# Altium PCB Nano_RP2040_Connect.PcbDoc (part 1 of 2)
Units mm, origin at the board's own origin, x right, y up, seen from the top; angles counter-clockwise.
Board outline 43.18 x 17.78 mm, 4 copper layers (TOP, GND, SIG, BOTTOM), stack 1.586 mm thick; 92 components, 78 nets, 388 pads, 198 vias.
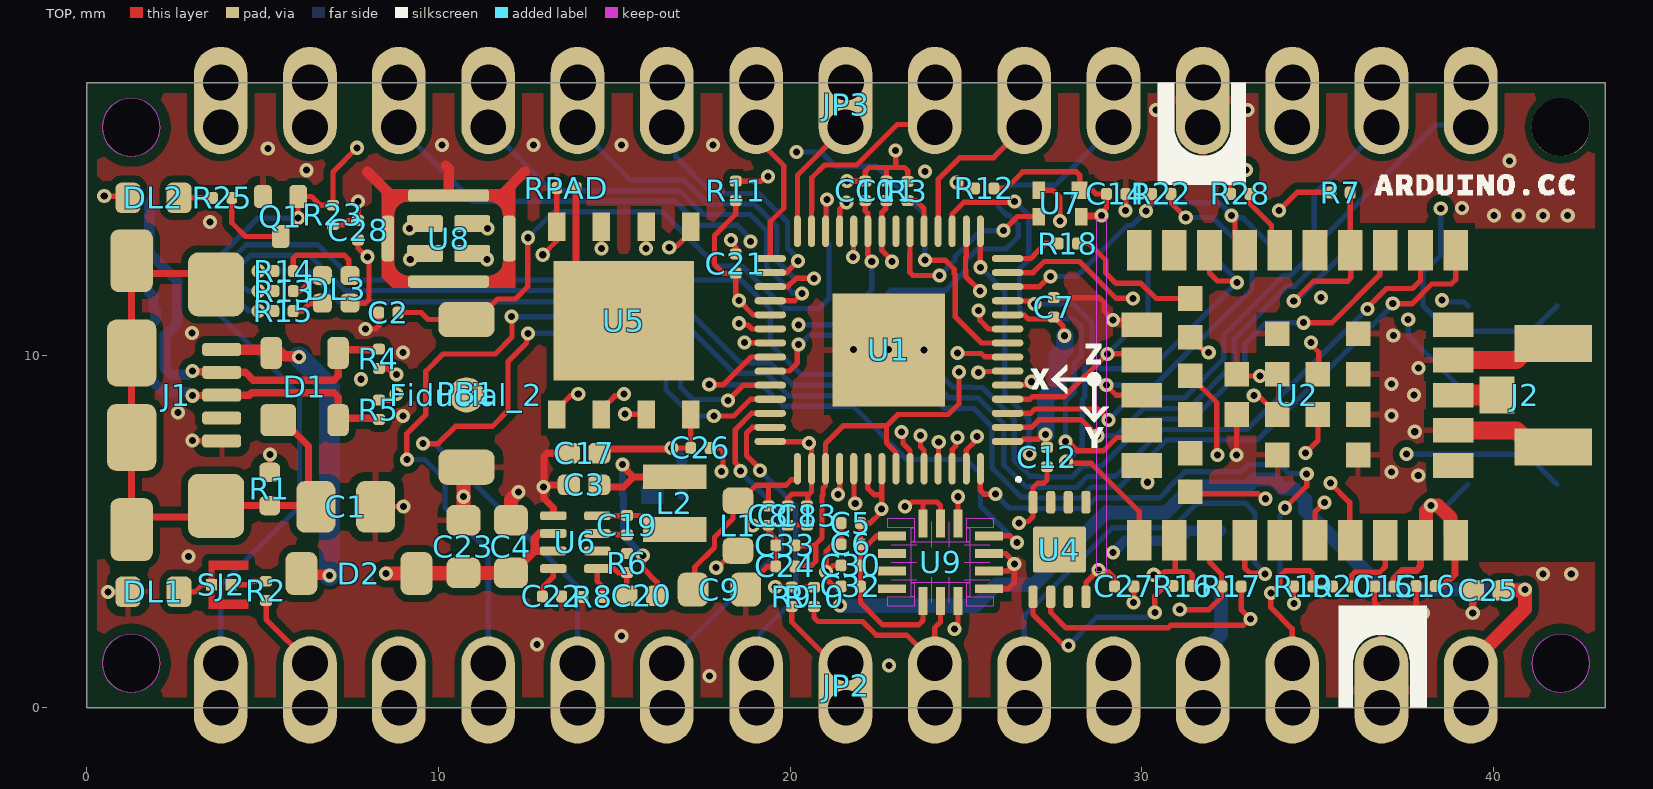
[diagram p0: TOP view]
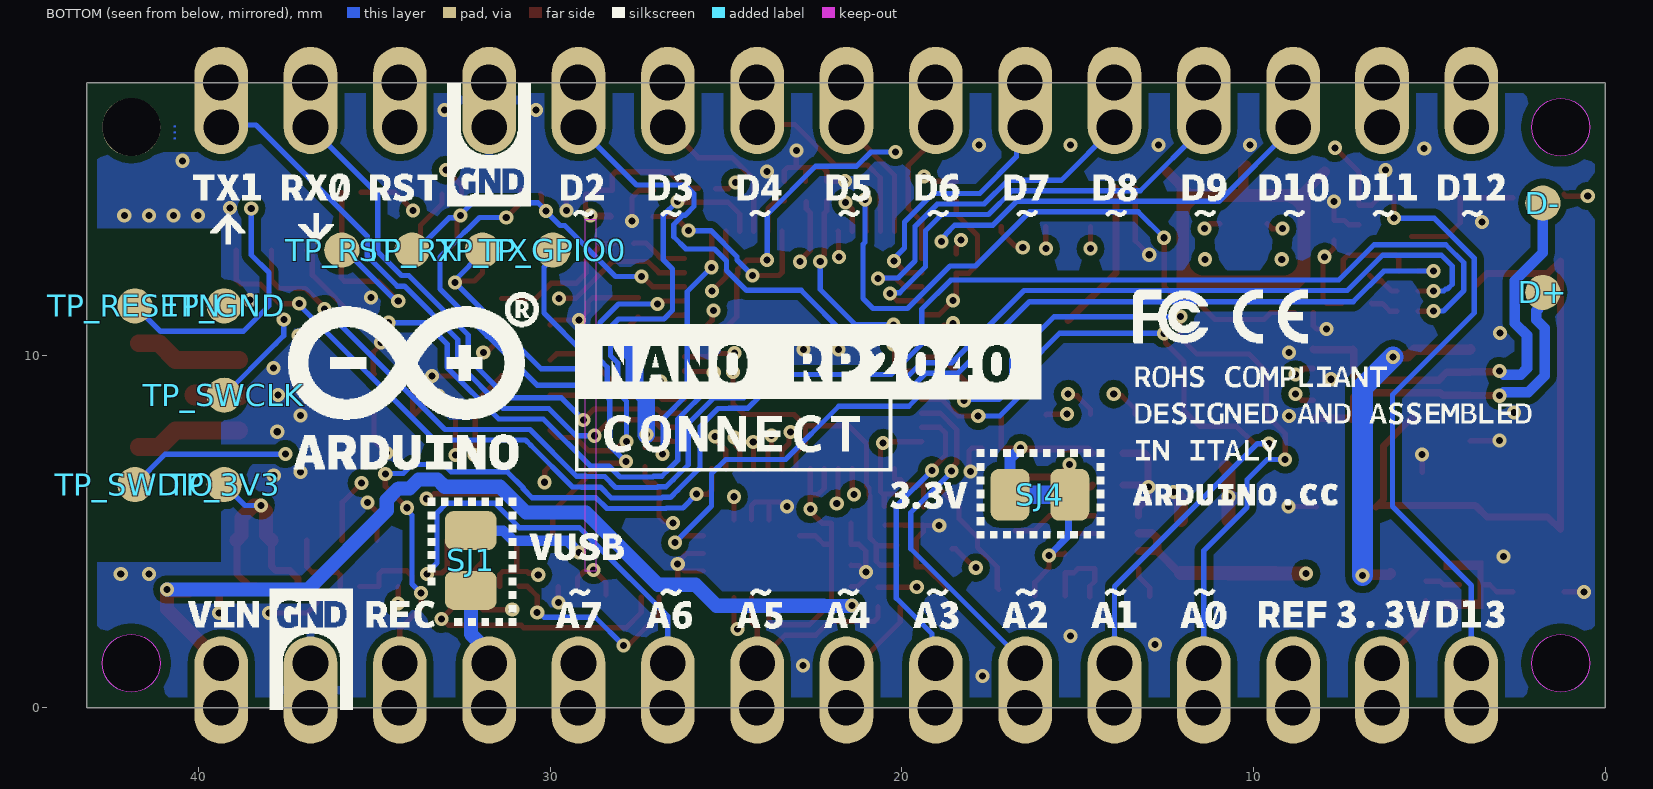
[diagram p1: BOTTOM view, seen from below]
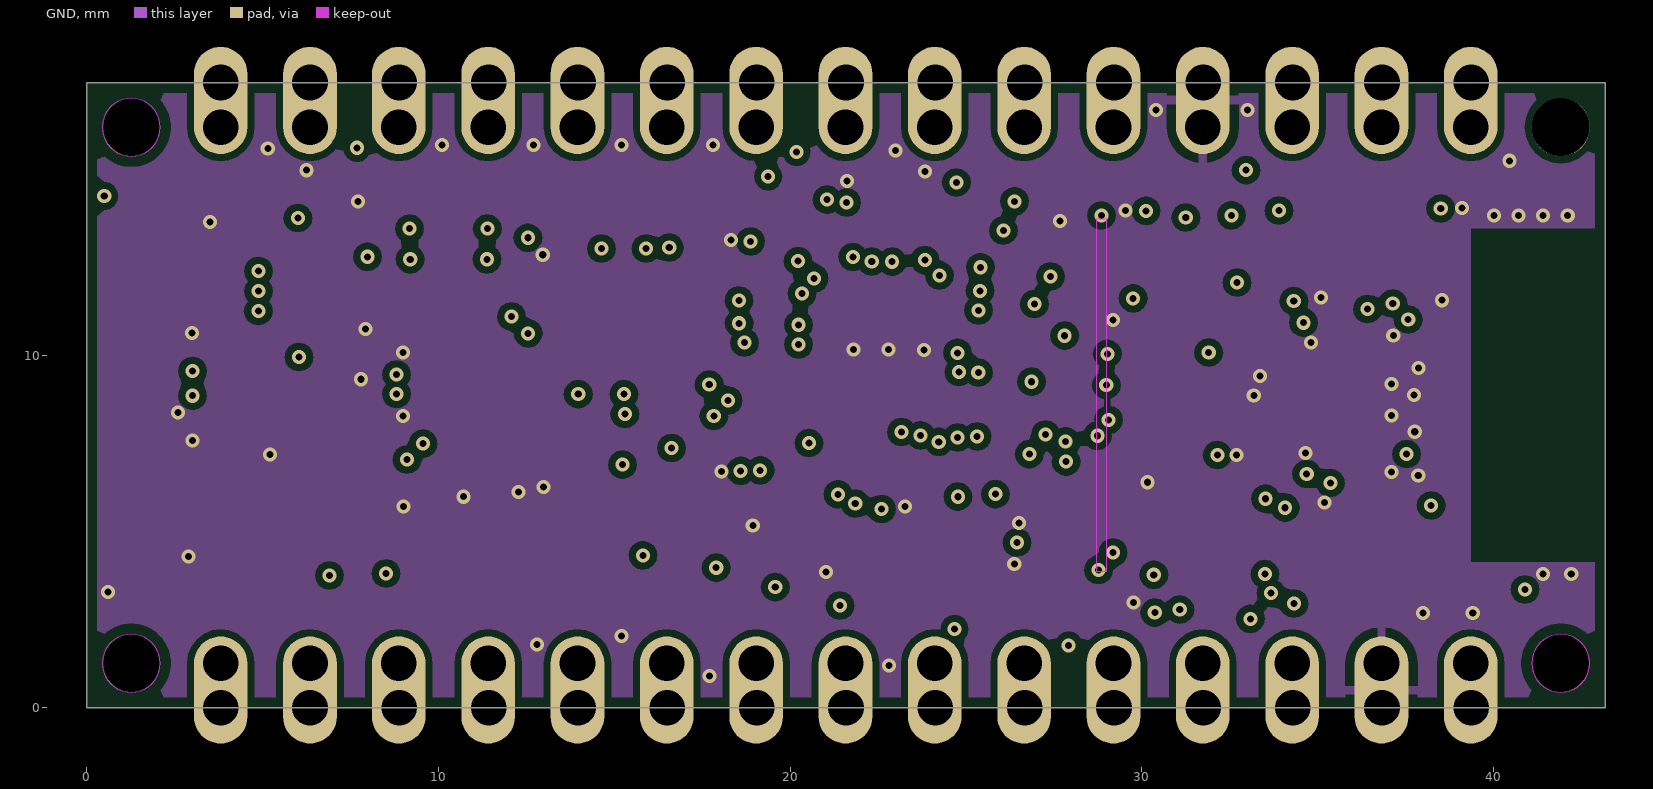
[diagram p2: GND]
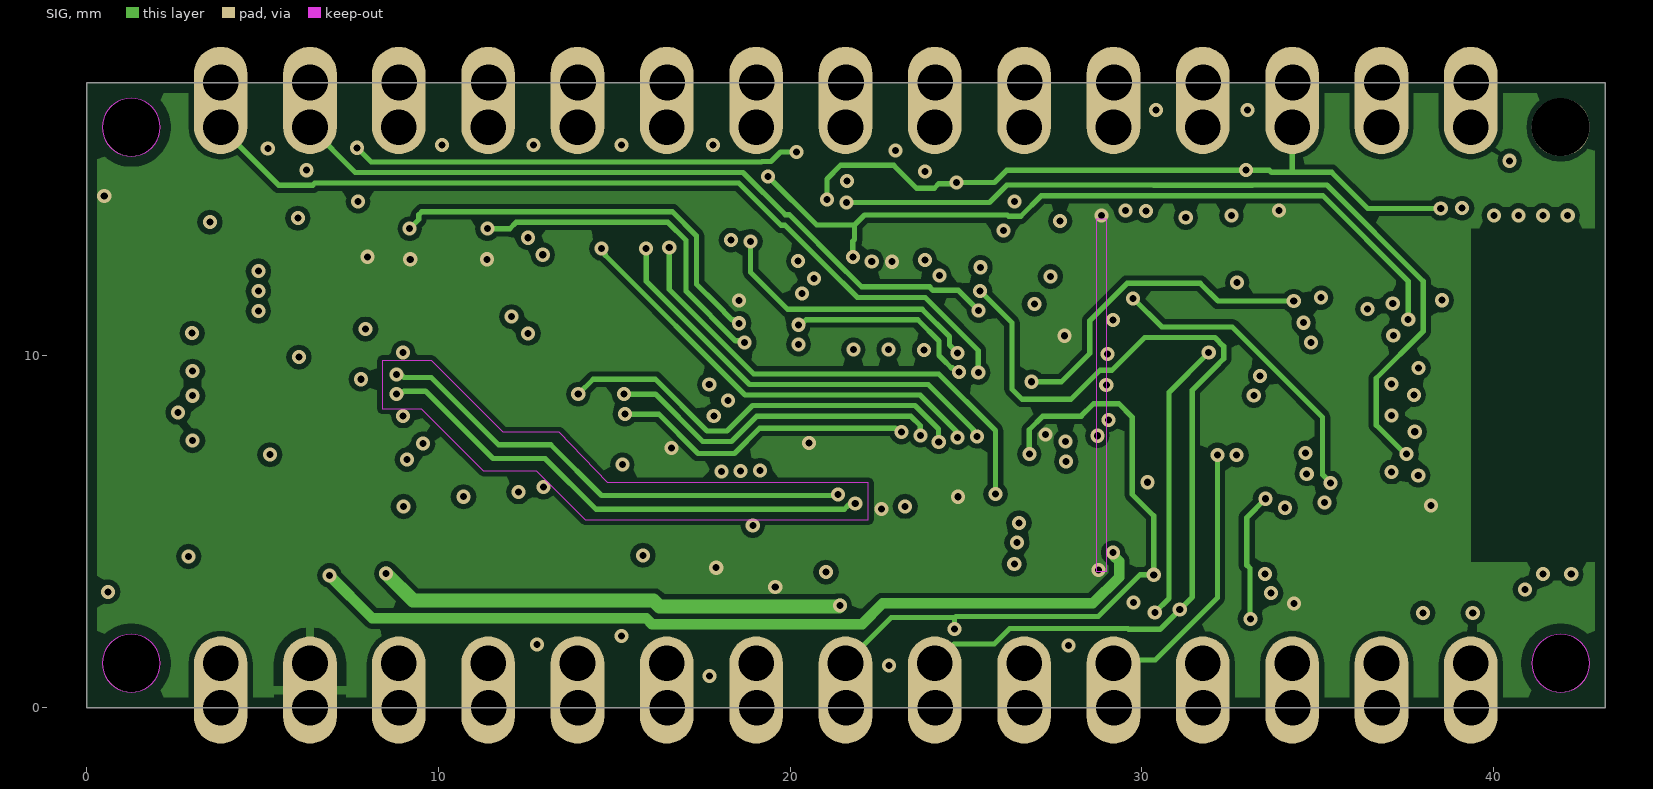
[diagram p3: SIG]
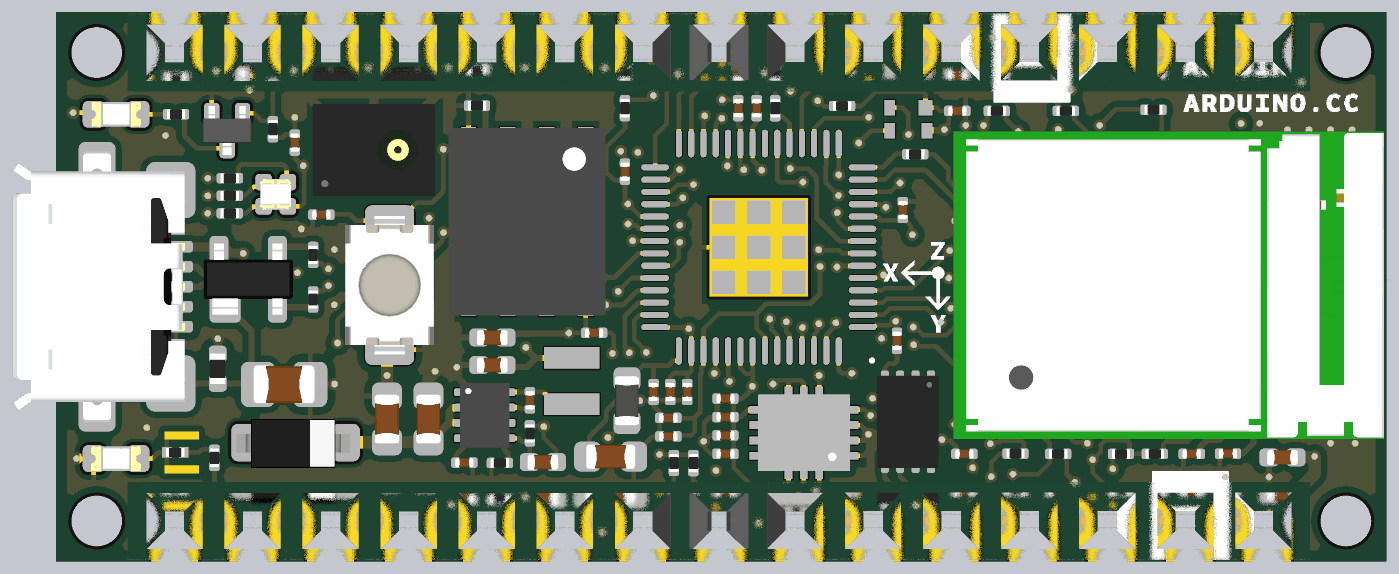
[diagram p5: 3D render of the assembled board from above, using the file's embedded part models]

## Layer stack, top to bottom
Top Solder: solder mask 0.0102, Solder Resist, Dk 3.5
TOP: signal copper 0.018
Dielectric 1: prepreg 0.14, PP-014, Dk 4.2
GND: signal copper 0.035
Dielectric2: core 1.2, FR-4, Dk 4.8
SIG: signal copper 0.035
Dielectric3: prepreg 0.14, PP-014, Dk 4.2
BOTTOM: signal copper 0.018
Bottom Solder: solder mask 0.0102, Solder Resist, Dk 3.5

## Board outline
43.174,-0.009 -0.006,-0.009 -0.006,17.771 43.174,17.771
cut-out: 41.904,0.436 ccw(c41.904,1.261) 42.73,1.261 ccw(c41.904,1.261) 41.904,2.087 ccw(c41.904,1.261) 41.079,1.261 ccw(c41.904,1.261)
cut-out: 1.264,15.676 ccw(c1.264,16.501) 2.09,16.501 ccw(c1.264,16.501) 1.264,17.327 ccw(c1.264,16.501) 0.439,16.501 ccw(c1.264,16.501)
cut-out: 1.264,0.436 ccw(c1.264,1.261) 2.09,1.261 ccw(c1.264,1.261) 1.264,2.087 ccw(c1.264,1.261) 0.439,1.261 ccw(c1.264,1.261)

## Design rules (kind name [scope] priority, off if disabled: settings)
BoardOutlineClearance Silks [(OnLayer('Top Overlay') OR OnLayer('Bottom Overlay'))] p1: gap=0.01 ignorepadtopadclearanceinfootprint=FALSE
BoardOutlineClearance MountingHoles [(ObjectKind = 'Pad') And (Name = 'Free-MH')] p2: gap=0 ignorepadtopadclearanceinfootprint=FALSE
BoardOutlineClearance Header_Castellated [((ObjectKind = 'Pad') And (Component = 'JP2')) OR                                                                                    ((ObjectKind = 'Pad') And (Component = 'JP3'))] p3: gap=0 ignorepadtopadclearanceinfootprint=FALSE
BoardOutlineClearance [All] p4: gap=0.3 ignorepadtopadclearanceinfootprint=FALSE
Clearance GND_POLYGONS [(InNamedPolygon('GND_TOP') OR InNamedPolygon('GND_2') OR InNamedPolygon('GND_3') OR InNamedPolygon('GND_BOT'))] p1: gap=0.2 ignorepadtopadclearanceinfootprint=FALSE
Clearance "Generic clearance 0.15mm" [All] p2: gap=0.15 ignorepadtopadclearanceinfootprint=FALSE
ComponentClearance NINA-UFL [InComponent('U2') vs InComponent('J2')] p1: gap=0 collisioncheckmode=3 verticalgap=0 showdistances=FALSE
ComponentClearance [All] p2: gap=0 collisioncheckmode=3 verticalgap=0 showdistances=FALSE
DiffPairsRouting [InDifferentialPairClass('USB')] p1: maxlimit=0.254 minlimit=0.15 mostfreqgap=0.254 toplayer_maxgap=0.15 toplayer_prefgap=0.15 toplayer_minwidth=0.15 toplayer_maxwidth=0.21 toplayer_prefwidth=0.21 midlayer14_mingap=0.24 midlayer14_maxgap=0.24 midlayer14_prefgap=0.24 midlayer14_minwidth=0.15 midlayer14_maxwidth=0.15 midlayer14_prefwidth=0.15 bottomlayer_maxgap=0.15 bottomlayer_prefgap=0.15 bottomlayer_minwidth=0.21 bottomlayer_maxwidth=0.21 bottomlayer_prefwidth=0.21 impedanceprofiledriven=TRUE impedanceprofileid={C5D8398E-BCA5-4495-8332-5063613C51E1} impedanceprofilevalue=90.000000 maxuncoupledlength=12.7
HoleSize [All] p1: absolutevalues=TRUE maxlimit=6 minlimit=0.2 maxpercent=80.000 minpercent=20.000
HoleToHoleClearance [All] p1: gap=0.25 allowstackedmicrovias=TRUE
MinimumAnnularRing [All] p1: minimumring=0.1
MinimumSolderMaskSliver [All] p1: minsoldermaskwidth=0.1
NetAntennae Inductor [(ObjectKind = 'Component') And (Comment = 'MAKK2016T3R3M')] p1: netantennaetolerance=10
NetAntennae [All] p2: netantennaetolerance=0
PolygonConnect [All] p1: thpad.connectstyle=Relief thpad.reliefconductorwidth=0.254 thpad.reliefentries=4 thpad.polygonreliefangle="90 Angle" thpad.airgapwidth=0.254 smdpad.connectstyle=Relief smdpad.reliefconductorwidth=0.15 smdpad.reliefentries=4 smdpad.polygonreliefangle="90 Angle" smdpad.airgapwidth=0.254 via.connectstyle=Direct via.reliefconductorwidth=0.254 via.reliefentries=4 via.polygonreliefangle="90 Angle" via.airgapwidth=0.254
RoomDefinition TOP [InComponentClass('TOP')] p1: confinementstyle=ConfineIn formatcopy=TRUE lockcomponents=FALSE outline -0.006,-0.009 43.174,-0.009 43.174,17.771 -0.006,17.771
RoutingVias [All] p1: holewidth=0.2 width=0.4 viastyle="Through Hole" minholewidth=0.2 minwidth=0.4 maxholewidth=0.2 maxwidth=0.4
ShortCircuit SJ4 [Component = 'SJ4' vs (InNet('+3V3') OR InNet('NetC3_2'))] p1: allowed=TRUE
ShortCircuit [All] p2: allowed=FALSE
SilkToSilkClearance [All] p1: silktosilkclearance=0.2
SilkToSolderMaskClearance [IsPad] p1: minsilkscreentomaskgap=0.1 clearancetoexposedcopper=TRUE
SolderMaskExpansion Solder_VIA [IsVia] p1: expansion=0.102 istentingtop=TRUE
SolderMaskExpansion [All] p2: expansion=0.102 istentingtop=FALSE
UnRoutedNet [All] p1: checkbadconnections=TRUE
ViasUnderSMD [All] p1: allowed=FALSE
Width [All] p1: maxlimit=5 minlimit=0.15 preferedwidth=0.15
20 further rules are at their usual default settings.

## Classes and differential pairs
net class 50ohm: ANT
differential pair class USB: D USB
pad class SMDPaste_OFF: D+-X D--X FD1-P$1 J3-4
differential pair USB: +USB_P -USB_N
differential pair D: +D_P -D_N

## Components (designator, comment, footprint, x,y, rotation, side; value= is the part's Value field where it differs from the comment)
C1 "C0805C472KDRACTU" CAP-0805 7.36,5.706 r180 top value=4.7nF
C2 "CL03A104KP3NNNC" CAP-0201 8.573,11.226 r180 top value=100nF
C3 "GRM155R60J106ME05D" CAP-0402 14.136,6.331 r0 top value=10µF
C4 "GRM188R61E106MA73J" CAP-0603 12.058,4.578 r270 top value=10µF
C5 "CL03A104KP3NNNC" CAP-0201 21.72,5.243 r180 top value=100nF
C6 "CL03A104KP3NNNC" CAP-0201 21.72,4.643 r180 top value=100nF
C7 "CL03A104KP3NNNC" CAP-0201 27.491,11.379 r90 top value=100nF
C8 "CL03A104KP3NNNC" CAP-0201 19.38,5.457 r270 top value=100nF
C9 "CC0603MRX5R5BB106" CAP-0603 17.985,3.355 r180 top value=10µF
C10 "CL03A104KP3NNNC" CAP-0201 22.134,14.691 r90 top value=100nF
C11 "CL03A104KP3NNNC" CAP-0201 22.734,14.691 r90 top value=100nF
C12 "CL03A104KP3NNNC" CAP-0201 27.299,7.122 r270 top value=100nF
C13 "GRM033R60J105MEA2D" CAP-0201 20.476,5.457 r270 top value=1µF
C14 "CL03A104KP3NNNC" CAP-0201 29.264,14.602 r0 top value=100nF
C15 "CL03A104KP3NNNC" CAP-0201 36.888,3.442 r180 top value=100nF
C16 "CL03A104KP3NNNC" CAP-0201 38.069,3.453 r180 top value=100nF
C17 "GRM155R60J106ME05D" CAP-0402 14.136,7.231 r0 top value=10µF
C18 "CL03A104KP3NNNC" CAP-0201 19.928,5.457 r270 top value=100nF
C19 "CL03A104KP3NNNC" CAP-0201 15.358,5.186 r270 top value=100nF
C20 "C0402C220J5GAC7411" CAP-0402 15.78,3.176 r0 top value=22pF
C21 "CL03A104KP3NNNC" CAP-0201 18.45,12.625 r90 top value=100nF
C22 "GRM033R60J105MEA2D" CAP-0201 13.225,3.16 r180 top value=1µF
C23 "GRM188R61E106MA73J" CAP-0603 10.708,4.578 r270 top value=10µF
C24 "CL03A104KP3NNNC" CAP-0201 19.862,4.014 r180 top value=100nF
C25 "C0402C105K8PACTU" CAP-0402 39.839,3.33 r0 top value=1µF
C26 "CL03A104KP3NNNC" CAP-0201 17.446,7.381 r0 top value=100nF
C27 "CL03A104KP3NNNC" CAP-0201 29.494,3.442 r0 top value=100nF
C28 "CL03A104KP3NNNC" CAP-0201 7.711,13.571 r90 top value=100nF
C30 "CL03A104KP3NNNC" CAP-0201 21.72,4.043 r180 top value=100nF
C32 "CL03A104KP3NNNC" CAP-0201 21.72,3.443 r180 top value=100nF
C33 "GRM033R60J105MEA2D" CAP-0201 19.862,4.614 r0 top value=1µF
D1 "PRTR5V0U2X,215" SOT190P230X110-4N 6.192,9.126 r0 top
D2 "D0026-A.2" SOD123-1 7.734,3.811 r180 top
D+ "CMP-018-0005-A.3" TP-1.00MM#1 1.772,11.802 r0 top
D- "CMP-018-0005-A.3" TP-1.00MM#1 1.772,14.342 r0 top
DL1 "HSMG-C190" LEDC1608X80N-AK 1.894,3.291 r0 top
DL2 "HSMD-C190" LEDC1608X80N-AK 1.894,14.491 r180 top
DL3 "SMLP34RGB2W3" SMLP34RGB2W 7.089,11.891 r90 top
Fiducial_2 "Fiducial mark 1mm with 2mm solder" "Fiducial mark 1mm with circle-Footprint-1" 10.794,8.891 r90 top
J1 "ZX62-AB-5PA(31)" ZX62-AB-5PA 1.274,8.881 r270 top
J2 "U.FL-R-SMT-1(60)" U.FL-R-SMT-1(60)-1 41.694,8.881 r270 top
JP2 "PINHD-1X15-NANO" PINHD-1X14_5VF#1 3.804,1.261 r180 top locked
JP3 "PINHD-1X15-NANO-DIGITAL-CASTELLATED" PINHD-1X14_5VF#2 39.364,16.501 r0 top locked
L1 "BLM18PG471SN1D" L-0603 18.514,5.173 r270 top
L2 "MAKK2016T3R3M" MAKK2016T3R3M-Footprint-1 16.718,5.814 r90 top
PB1 "IT-1185AP1C-160G-GTR" C&K_PTS820_NO_HOLES-1 10.794,8.933 r90 top
Q1 "2N7002T-7-F" SOT523 5.508,13.961 r180 top
R1 "CRCW04021M00FKED" RES-0402 5.201,6.214 r270 top value=1M
R2 "AC0201FR-07330RL" RES-0201 5.094,3.316 r270 top value=330
R3 "CRCW02010000Z0ED" RES-0201 23.338,14.687 r90 top value=0
R4 "CRCW020127R0FNED" RES-0201 8.304,9.916 r270 top value=27R
R5 "CRCW020127R0FNED" RES-0201 8.304,8.466 r90 top value=27R
R6 "RMCF0201FT976K" RES-0201 15.358,4.109 r90 top value=976k
R7 "AC0201FR-07220KL" RES-0201 35.644,14.639 r180 top value=220k
R8 "AC0201FR-07220KL" RES-0201 14.377,3.149 r0 top value=220k
R9 "RC0201FR-074K7L" RES-0201 20.043,3.147 r90 top value=4.7k
R10 "RC0201FR-074K7L" RES-0201 20.676,3.146 r90 top value=4.7k
R11 "RC0201FR-074K7L" RES-0201 18.45,14.691 r270 top value=4.7k
R12 "RC0201FR-074K7L" RES-0201 25.513,14.762 r0 top value=4.7k
R13 "AC0201FR-07330RL" RES-0201 5.594,11.841 r180 top value=330
R14 "AC0201FR-07330RL" RES-0201 5.594,12.412 r180 top value=330
R15 "AC0201FR-07330RL" RES-0201 5.591,11.271 r180 top value=330
R16 "CRCW02010000Z0ED" RES-0201 31.155,3.453 r180 top value=0
R17 "CRCW02010000Z0ED" RES-0201 32.544,3.442 r0 top value=0
R18 "CRCW02010000Z0ED" RES-0201 27.894,13.191 r0 top value=0
R19 "RC0201FR-074K7L" RES-0201 34.588,3.442 r180 top value=4.7k
R20 "CRCW02010000Z0ED" RES-0201 35.688,3.442 r180 top value=0
R22 "CRCW02010000Z0ED" RES-0201 30.546,14.602 r180 top value=0
R23 "RMCF0201FT976K" RES-0201 6.996,14.006 r90 top value=976k
R25 "AC0201FR-07330RL" RES-0201 3.844,14.491 r0 top value=330
R28 "CRCW02010000Z0ED" RES-0201 32.794,14.602 r180 top value=0
RPAD "CRCW02010000Z0ED" RES-0201 13.636,14.771 r180 top value=0
SJ1 "SMD solder JUMPER 0805" SJ#1 32.252,4.182 r270 bottom
SJ2 "Solder Jumper 0201 CLOSED with HUG" "Solder Jumper Maze-Footprint-1" 3.819,3.491 r270 top
SJ4 "SMD solder JUMPER CLOSED" SJ#2 16.071,6.052 r180 bottom
TP_3V3 "CMP-018-0005-A.3" TP-1.00MM#2 39.263,6.341 r90 bottom
TP_GND "CMP-018-0005-A.3" TP-1.00MM#2 39.263,11.421 r90 bottom
TP_GPIO0 "CMP-018-0005-A.3" TP-1.00MM#2 29.919,13.006 r90 bottom
TP_RESETN "CMP-018-0005-A.3" TP-1.00MM#2 41.803,11.421 r90 bottom
TP_RST "CMP-018-0005-A.3" TP-1.00MM#2 35.919,13.006 r90 bottom
TP_RX "CMP-018-0005-A.3" TP-1.00MM#2 33.919,13.006 r90 bottom
TP_SWCLK "CMP-018-0005-A.3" TP-1.00MM#2 39.263,8.881 r90 bottom
TP_SWDIO "CMP-018-0005-A.3" TP-1.00MM#2 41.803,6.341 r90 bottom
TP_TX "CMP-018-0005-A.3" TP-1.00MM#2 31.919,13.006 r90 bottom
U1 "RP2040" QFN40P700X700X90_HS-57N 22.804,10.166 r180 top locked
U2 "NINA-W102-00B" NINA-W102 34.869,8.881 r180 top locked
U4 "ATECC608A-MAHDA-T" UDFN8 27.654,4.491 r180 top
U5 "AT25SF128A-MHB-T" PSON127P600X60_HS-9N 15.266,11.001 r270 top
U6 "MP2322GQH" QFN50P150X200X90-8L 13.888,4.701 r0 top
U7 "DSC6111HI2B-012.0000" DFN120P120X89-4M 27.672,14.333 r180 top
U8 "MP34DT06JTR" HCLGA 10.284,13.334 r0 top
U9 "LSM6DSOXTR" VFLGA14 24.271,4.131 r180 top

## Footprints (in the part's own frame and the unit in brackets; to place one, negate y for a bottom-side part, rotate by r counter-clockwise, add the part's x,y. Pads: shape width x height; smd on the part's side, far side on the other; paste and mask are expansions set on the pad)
C&K_PTS820_NO_HOLES-1 [mm]
  rrect49% 1x1.6 smd mask+0.05: 1(-2.1,0) 2(2.1,0)
  body extent -2.25,-1.45 2.25,1.45, height 2
CAP-0201 [mm] "Chip Capacitor, 2-Leads, Body 0201 (in) 0603 (mm) IPC Medium Density"
  rrect52% 0.31x0.34 smd mask+0: 1(-0.275,0) 2(0.275,0)
  body extent -0.3,-0.15 0.3,0.15, height 0.3
CAP-0402 [mm] "Chip Capacitor, 2-Leads, Body  0402 (in) 1005 (mm), IPC Medium Density"
  rrect52% 0.63x0.58 smd mask+0: 1(-0.435,0) 2(0.435,0)
  body extent -0.5,-0.25 0.5,0.25, height 0.5
CAP-0603 [mm] "Chip Capacitor, Body 0603 imperial,1.6x0.8mm, IPC High Density"
  rrect51% 0.87x0.97 smd mask+0: 1(-0.75,0) 2(0.75,0)
  body extent -0.8,-0.4 0.8,0.4, height 0.8
CAP-0805 [mm] "Chip Capacitor, Body 0805 imperial, 2.0x1.2mm, IPC Medium Density"
  rrect45% 1.11x1.47 smd mask+0: 1(-0.85,0) 2(0.85,0)
  body extent -1,-0.62 1,0.63, height 1.25
DFN120P120X89-4M [mm] "DFN, 4-Leads, Body 1,60x1,20mm, Pitch 1,20mm, IPC Low Density"
  rect 0.45x0.5 smd mask+0.04: 1(-0.555,-0.375)
  rect 0.35x0.5 smd mask+0.04: 2(0.605,-0.375) 3(0.605,0.375) 4(-0.605,0.375)
  body extent -0.8,-0.6 0.8,0.6, height 0.9
"Fiducial mark 1mm with circle-Footprint-1" [mm]
  round 1 smd paste-10 mask+0.5: 1(0,0)
  TOP pour cut-out: 0,1 0.383,0.924 0.707,0.707 0.924,0.383 1,0 1,0 0.924,-0.383 0.707,-0.707 0.383,-0.924 0,-1 0,-1 -0.383,-0.924 -0.707,-0.707 -0.924,-0.383 -1,0 -1,0 -0.924,0.383 -0.707,0.707 -0.383,0.924 0,1
HCLGA [mm]
  rrect22% 1.02x0.48 smd paste+0 mask+0: 1(-0.675,-0.425) 2(0.675,-0.425) 3(0.675,0.425) 4(-0.675,0.425)
  rrect50% 0.35x1.3 smd paste+0 mask+0: 5(-1.725,0) 5(1.725,0)
  rrect50% 2.3x0.35 smd paste+0 mask+0: 5(0,-1.225) 5(0,1.225)
  TOP region: 1.9,0 1.9,1.4 -1.9,1.4 -1.9,-1.1 -1.6,-1.4 1.9,-1.4 1.9,0 1.55,0 1.55,-0.65 1.52,-0.803 1.433,-0.933 1.303,-1.02 1.15,-1.05 1.15,-1.05 -1.15,-1.05 -1.303,-1.02 -1.433,-0.933 -1.52,-0.803 -1.55,-0.65 -1.55,-0.65 -1.55,0.65 -1.52,0.803 -1.433,0.933 -1.303,1.02 -1.15,1.05 -1.15,1.05 1.15,1.05 1.303,1.02 1.433,0.933 1.52,0.803 1.55,0.65 1.55,0.65 1.55,0
  body extent -2,-1.5 2,1.5, height 1
L-0603 [mm] "Chip Inductor - Body 0603 imperial,1.6x0.8mm, IPC High Density"
  rrect51% 0.75x0.87 smd mask+0: 1(-0.71,0) 2(0.71,0)
  body extent -0.8,-0.4 0.8,0.4, height 0.8
LEDC1608X80N-AK [mm]
  rrect50% 0.72x0.87 smd: A(0.725,0) C(-0.725,0)
  body extent -0.8,-0.4 0.8,0.4, height 0.79
MAKK2016T3R3M-Footprint-1 [mm]
  rect 0.7x1.8 smd mask+0.05: 1(-0.75,0) 2(0.75,0)
  body extent -1,-0.8 1,0.8, height 1
NINA-W102 [mm]
  rect 0.7x1.15 smd mask+0.05: 1(4.95,4.125) 2(3.95,4.125) 3(2.95,4.125) 4(1.95,4.125) 5(0.95,4.125) 6(-0.05,4.125) 7(-1.05,4.125) 8(-2.05,4.125) 9(-3.05,4.125) 10(-4.05,4.125) 16(-4.05,-4.125) 17(-3.05,-4.125) 18(-2.05,-4.125) 19(-1.05,-4.125) 20(-0.05,-4.125) 21(0.95,-4.125) 22(1.95,-4.125) 23(2.95,-4.125) 24(3.95,-4.125) 25(4.95,-4.125)
  rect 1.15x0.7 smd mask+0.05: 11(-3.975,2) 12(-3.975,1) 13(-3.975,0) 14(-3.975,-1) 15(-3.975,-2) 26(4.875,-2) 27(4.875,-1) 28(4.875,0) 29(4.875,1) 30(4.875,2)
  rect 0.7x0.7 smd mask+0.05: 31(3.5,2.75) 32(3.5,1.65) 33(3.5,0.55) 34(3.5,-0.55) 35(3.5,-1.65) 36(3.5,-2.75) GND1(-1.28,1.7) GND2(-1.28,0.55) GND3(-1.28,-0.6) GND4(-1.28,-1.75) GND5(-0.13,0.55) GND6(-0.13,-0.6) GND7(1.02,1.7) GND8(1.02,0.55) GND9(1.02,-0.6) GND10(1.02,-1.75) GND11(2.17,0.55) GND12(2.17,-0.6)
  Keep-Out Layer region: 5.865,-5 6.165,-5 6.165,5 5.865,5
  body extent -8.27,-5.05 5.73,4.95, height 3.81
PINHD-1X14_5VF#1 [mil]
  round 27.56 hole 40 mask+7.87: 1(0,50) 2(-100,50) 3(-200,50) 4(-300,50) 5(-400,50) 6(-500,50) 7(-600,50) 8(-700,50) 9(-800,50) 10(-900,50) 11(-1000,50) 12(-1100,50) 13(-1200,50) 14(-1300,50) 15(-1400,50)
  oval 60x120 hole 40 copper offset 0,30 paste-100: 1(0,0) 2(-100,0) 3(-199.41,0) 4(-299.41,0) 5(-399.41,0) 6(-499.41,0) 7(-599.41,0) 8(-699.41,0) 9(-799.41,0) 10(-899.41,0) 11(-999.41,0) 12(-1099.41,0) 13(-1199.41,0) 14(-1299.41,0) 15(-1399.41,0)
  body extent -1454,-50 60,50, height 335
PINHD-1X14_5VF#2 [mil]
  oval 60x120 hole 40 copper offset 0,30 paste-100: 1(-0.59,0) 2(-100.59,0) 3(-200.59,0) 4(-300.59,0) 5(-400.59,0) 6(-500.59,0) 7(-600.59,0) 8(-700.59,0) 9(-800.59,0) 10(-900.59,0) 11(-1000.59,0) 12(-1100.59,0) 13(-1200.59,0) 14(-1300,0) 15(-1400,0)
  round 27.56 hole 40 mask+7.87: 1(0,50) 2(-100,50) 3(-200,50) 4(-300,50) 5(-400,50) 6(-500,50) 7(-600,50) 8(-700,50) 9(-800,50) 10(-900,50) 11(-1000,50) 12(-1100,50) 13(-1200,50) 14(-1300,50) 15(-1400,50)
  body extent -1460,-50 54,50, height 335
PSON127P600X60_HS-9N [mm] "PSON, 8-Leads, Body 5,00x6,00mm, Pitch 1,27mm, Thermal Pad 4,00x3,40mm, IPC Medium Density"
  rect 0.8x0.5 smd mask+0.05: 1(-2.67,1.905) 2(-2.67,0.635) 3(-2.67,-0.635) 4(-2.67,-1.905) 5(2.67,-1.905) 6(2.67,-0.635) 7(2.67,0.635) 8(2.67,1.905)
  rect 3.4x4 smd paste-10 mask+0.05: 9(0,0)
  body extent -3.05,-2.55 3.05,2.55, height 0.6
QFN40P700X700X90_HS-57N [mm] "QFN, 56-Leads, Body 7,00x7,00mm, Pitch 0,40mm, Thermal Pad 3,10x3,10mm, IPC Medium Density"
  oval 0.9x0.2 smd mask+0.03: 1(-3.375,2.6) 2(-3.375,2.2) 3(-3.375,1.8) 4(-3.375,1.4) 5(-3.375,1) 6(-3.375,0.6) 7(-3.375,0.2) 8(-3.375,-0.2) 9(-3.375,-0.6) 10(-3.375,-1) 11(-3.375,-1.4) 12(-3.375,-1.8) 13(-3.375,-2.2) 14(-3.375,-2.6) 29(3.375,-2.6) 30(3.375,-2.2) 31(3.375,-1.8) 32(3.375,-1.4) 33(3.375,-1) 34(3.375,-0.6) 35(3.375,-0.2) 36(3.375,0.2) 37(3.375,0.6) 38(3.375,1) 39(3.375,1.4) 40(3.375,1.8) 41(3.375,2.2) 42(3.375,2.6)
  oval 0.2x0.9 smd mask+0.03: 15(-2.6,-3.375) 16(-2.2,-3.375) 17(-1.8,-3.375) 18(-1.4,-3.375) 19(-1,-3.375) 20(-0.6,-3.375) 21(-0.2,-3.375) 22(0.2,-3.375) 23(0.6,-3.375) 24(1,-3.375) 25(1.4,-3.375) 26(1.8,-3.375) 27(2.2,-3.375) 28(2.6,-3.375) 43(2.6,3.375) 44(2.2,3.375) 45(1.8,3.375) 46(1.4,3.375) 47(1,3.375) 48(0.6,3.375) 49(0.2,3.375) 50(-0.2,3.375) 51(-0.6,3.375) 52(-1,3.375) 53(-1.4,3.375) 54(-1.8,3.375) 55(-2.2,3.375) 56(-2.6,3.375)
  rect 3.2x3.2 smd paste-5: 57(0,0)
  silkscreen extent -3.73,3.63 -3.63,3.73, body extent -3.5,-3.5 3.5,3.5, height 0.9
QFN50P150X200X90-8L [mm] "QFN, 8-Leads, Body 1,50x2,00mm, Pitch 0,50mm, IPC High Density"
  rrect50% 0.75x0.25 smd mask+0.05: 1(-0.625,0.75) 2(-0.625,0.25) 3(-0.625,-0.25) 4(-0.625,-0.75) 5(0.625,-0.75) 6(0.625,-0.25) 7(0.625,0.25) 8(0.625,0.75)
  body extent -0.8,-1.05 0.8,1.05, height 0.9
RES-0201 [mm] "Chip Resistor, 2-Leads, Body 0201 (in) 0603 (mm) IPC Medium Density"
  rrect52% 0.31x0.34 smd mask+0: 1(-0.275,0) 2(0.275,0)
  body extent -0.3,-0.15 0.3,0.15, height 0.24
RES-0402 [mm] "Chip Resistor, 2-Leads, Body  0402 (in) 1005 (mm), IPC Medium Density"
  rrect51% 0.55x0.58 smd mask+0: 1(-0.475,0) 2(0.475,0)
  body extent -0.5,-0.25 0.5,0.25, height 0.34
SJ#1 [mm]
  rrect45% 1.11x1.47 smd: 1(-0.85,0) 2(0.85,0)
SJ#2 [mm]
  rrect45% 1.11x1.47 smd mask+0: 1(-0.85,0) 2(0.85,0)
  TOP region: -0.31,0.254 -0.31,-0.254 0.31,-0.254 0.31,0.254
SMLP34RGB2W [mm]
  rrect52% 0.54x0.54 smd: 1(-0.395,-0.395) 2(-0.395,0.395) 3(0.395,0.395) 4(0.395,-0.395)
  body extent -0.5,-0.5 0.5,0.5, height 0.2
SOD123-1 [mm]
  rrect50% 0.91x1.22 smd: A(1.635,0) C(-1.635,0)
  body extent -1.78,-0.78 1.92,0.82, height 1.27
"Solder Jumper Maze-Footprint-1" [mm]
  rect 0.34x0.31 smd mask+0: 1(0,-0.275) 2(0,0.275)
  TOP region: -0.424,0.77 -0.424,-0.2 0.424,-0.2 0.424,0.77 0.678,0.77 0.678,-0.35 -0.678,-0.35 -0.678,0.77
  body extent -0.15,-0.3 0.15,0.3, height 0.24
SOT190P230X110-4N [mm]
  rrect33% 1.01x0.91 smd paste+0 mask+0: 1(-0.75,-0.955)
  rrect49% 0.61x0.91 smd paste+0 mask+0: 2(0.95,-0.955) 3(0.95,0.955) 4(-0.95,0.955)
  body extent -1.45,-1.15 1.45,1.15, height 1
SOT523 [mm]
  rrect50% 0.5x0.66 smd: D(0,0.57) G(-0.5,-0.57) S(0.5,-0.57)
  body extent -0.8,-0.8 0.8,0.8, height 0.8
TP-1.00MM#1 [mm]
  rrect100% 1x1 smd far side paste-2.54: X(0,0)
TP-1.00MM#2 [mm]
  rrect100% 1x1 smd paste-2.54: X(0,0)
U.FL-R-SMT-1(60)-1 [mm]
  rect 1.05x2.2 smd paste-3: GND(-1.475,0) GND(1.475,0)
  rect 1.05x1 smd paste-3: SIG(0,-1.6)
  body extent -1.5,-1.55 1.5,1.55, height 1.25
UDFN8 [mm] "QFN, 8-Leads, Body 3.00x2.00mm, Pitch 0.50mm, Thermal Pad 1.30x1.50mm, IPC Medium Density"
  rrect54% 0.26x0.64 smd paste+0 mask+0: 1(-0.75,-1.345) 2(-0.25,-1.345) 3(0.25,-1.345) 4(0.75,-1.345) 5(0.75,1.345) 6(0.25,1.345) 7(-0.25,1.345) 8(-0.75,1.345)
  rrect8% 1.5x1.3 smd paste-1.5 mask+0: 9(0,0)
  body extent -1,-1.5 1,1.5, height 0.55
VFLGA14 [mm]
  rect 0.8x0.25 smd mask+0.05: 1(-1.375,0.75) 2(-1.375,0.25) 3(-1.375,-0.25) 4(-1.375,-0.75) 8(1.375,-0.75) 9(1.375,-0.25) 10(1.375,0.25) 11(1.375,0.75)
  rect 0.25x0.8 smd mask+0.05: 5(-0.5,-1.1) 6(0,-1.1) 7(0.5,-1.1) 12(0.5,1.1) 13(0,1.1) 14(-0.5,1.1)
  TOP keep-out region: -0.83,-0.98 -0.83,-0.58 -0.74,-0.58 -0.74,-0.98
  TOP keep-out region: 0.74,-0.98 0.74,-0.58 0.83,-0.58 0.83,-0.98
  TOP keep-out region: 0.74,0.58 0.74,0.98 0.83,0.98 0.83,0.58
  TOP keep-out region: -0.83,0.58 -0.83,0.98 -0.74,0.98 -0.74,0.58
  TOP keep-out region: -1.5,-1.25 -1.5,-0.98 -0.74,-0.98 -0.74,-1.25
  TOP keep-out region: 0.74,-1.25 0.74,-0.98 1.5,-0.98 1.5,-1.25
  TOP keep-out region: 0.74,0.98 0.74,1.25 1.5,1.25 1.5,0.98
  TOP keep-out region: -1.5,0.98 -1.5,1.25 -0.74,1.25 -0.74,0.98
  TOP keep-out region: -0.83,-0.58 -0.83,0.58 0.83,0.58 0.83,-0.58
  TOP keep-out lines w0.01: 1.4,0.5 0.67,0.5 ; 1.4,0 0.67,0 ; 1.4,-0.5 0.67,-0.5 ; 0.25,1.15 0.25,0.42 ; 0.25,-0.42 0.25,-1.15 ; -0.25,1.15 -0.25,0.42 ; -0.25,-0.42 -0.25,-1.15 ; -0.67,0.5 -1.4,0.5 ; -0.67,0 -1.4,0 ; -0.67,-0.5 -1.4,-0.5
  body extent -1.5,-1.25 1.5,1.25, height 0.76
ZX62-AB-5PA [mm]
  rrect49% 0.37x1.11 smd paste+0 mask+0: 1(-1.3,2.56) 2(-0.65,2.56) 3(0,2.56) 4(0.65,2.56) 5(1.3,2.56)
  rrect37% 1.825x1.6 smd paste+0 mask+0: M1(-3.147,2.4) M4(3.147,2.4)
  rrect37% 1.78x1.2 smd paste+0 mask+0: M2(-3.82,0) M3(3.82,0)
  rrect37% 1.9x1.4 smd paste+0 mask+0: M5(-1.2,0) M6(1.2,0)
  body extent -4.4,-2.75 4.4,2.85, height 2.75

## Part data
C1: library part C0059-A.9, "CAP CHIP 0805 4.7nF 1000V X7R 10%", Case Code (Imperial)=0805, Case Code (Metric)=2012, Dielectric=X7R, Manufacturer=KEMET, Tolerance=10%, Voltage=1kV
C2 C5 C6 C7 C8 C10 C11 C12 C14 C15 C16 C18 C19 C21 C24 C26 C27 C28 C30 C32: library part C0113-A.1, "CAP CHIP 0201 100nF 10V X5R 10%", Case Code (Imperial)=0201, Case Code (Metric)=0603, Dielectric=X5R, Manufacturer="Samsung Electro-Mechanics", Tolerance=10%, Voltage=10V
C3 C17: library part C0091-A.8, "CAP CHIP 0402 10UF X5R 6.3V 20%", Case Code (Imperial)=0402, Case Code (Metric)=1005, Dielectric=X5R, Manufacturer=Murata, Tolerance=20%, Voltage=6.3V
C4 C23: library part C0047-A.12, "CAP CHIP 0603 10uF 25V X5R 20%", Case Code (Imperial)=0603, Case Code (Metric)=1608, Dielectric=X5R, Manufacturer=Murata, Manufacturer 2=Samsung, Manufacturer Part Number 2=CL10A226MPCNUBE, Part Number=C1608X5R1A226MT000N, Tolerance=20%, Voltage=25V
C9: library part C0046-A.9, "CAP CHIP 0603 10uF 6V3 X5R 20% Bob", Case Code (Imperial)=0603, Case Code (Metric)=1608, Dielectric=X5R, Manufacturer=Yageo, Tolerance=20%, Voltage=6.3V
C13 C22 C33: library part C0002-A.9, "CAP CHIP 0201 1UF 6.3V X5R 20%", Case Code (Imperial)=0201, Case Code (Metric)=0603, Dielectric=X5R, Manufacturer=Murata, Tolerance=20%, Voltage=6.3V
C20: library part C0029-A.9, "CAP CHIP 0402 22pF 50V C0G 5%", Case Code (Imperial)=0402, Case Code (Metric)=1005, Dielectric=C0G, Manufacturer=KEMET, Manufacturer 2=AVX, Manufacturer Part Number 2=04025A220JAT2A, Tolerance=5%, Voltage=50V
C25: library part C0017-A.9, "CAP CHIP 0402 1uF 10V X5R 10%", Case Code (Imperial)=0402, Case Code (Metric)=1005, Dielectric=X5R, Manufacturer=KEMET, Manufacturer 2=AVX, Manufacturer Part Number 2=GRM155R61A105KE15D, Tolerance=10%, Voltage=10V
D1: library part D0025-A.3, "TVS ARRAY 4LIN.8kV 1pF SOT143B", Manufacturer=Nexperia
D2: "DIODE SCHOTTKY SMD 1A 40V SOD123FL", Manufacturer=Nexperia, Part Number=PMEG6020AELRX
D+ D- TP_3V3 TP_GND TP_GPIO0 TP_RESETN TP_RST TP_RX TP_SWCLK TP_SWDIO TP_TX: library part UT0013-A.2, "Test point 1.00mm"
DL1: library part L0009-A.4, "LED SMD 0603 GREEN/568 15mcd 120^", Manufacturer=Broadcom
DL2: library part L0007-A.4, "LED SMD 0603 ORANGE604 8mcd DIFF.", Manufacturer=Broadcom
DL3: library part L0014-A.5, "LED RGB DIFFUSED PICOLED SMD", Case Code (Imperial)=0404, Case Code (Metric)=1010, Color=Blue,Green,Red, Forward Current=20mA, Forward Voltage=3V, Lens Color=White, Manufacturer="ROHM Semiconductor", Max Operating Temperature=85°C, Min Operating Temperature=-40°C, Package Quantity=1, Test Current=5mA
Fiducial_2: library part UT0024-A.6
J1: library part J0039-A.5, "CONN USB MICRO F/90^ SMD TipoAB 5x1", Manufacturer=Hirose
J2: library part J0042-A.4, "CONN Micro UFL NO PASTE", Manufacturer=Hirose
JP2: library part J0055-A.4, "CONN THD SOCKET F/1/D 15V JANALOG NANO-TYPE"
JP3: library part J0183-A.1, "CONN THD SOCKET F/1/D 15V JDIGITAL NANO-TYPE CASTELLATED"
L1: library part I0006-A.3, "FERRITE SMD 0603 470R 1A 0.2R", Case Code (Imperial)=0603, Case Code (Metric)=1608, Current=1A, DC Resistance (DCR)=200mR, Manufacturer=Murata, Max Operating Temperature=125°C, Min Operating Temperature=-55°C, Package Quantity=1, Test Frequency=100MHz, Tolerance=25%
L2: library part I0045-A.6, "IND CHIP 0806 3.3 uH 20% 1.2A", Case Code (Imperial)=0806, Case Code (Metric)=2016, Current Rating=1.2A, DC Resistance (DCR)=255mR, Inductance=3.3uH, Manufacturer="Taiyo Yuden", Manufacturer 2=Murata, Manufacturer Part Number 2=LQM2MPN3R3NG0L, Max DC Current=1.15A, Max Operating Temperature=105°C, Min Operating Temperature=-40°C, Package Quantity=3000, Resistor Type=Wirewound, Test Frequency=2MHz, Tolerance=20%
PB1: library part B0001-A.7, "PUSHBUTTON WHITE NO ANCHORS", Color=White, Manufacturer=Switronic
Q1: library part T0003-A.2, "MOSFET N-CH 60V 115mA SOT523", Manufacturer="Diodes Inc."
R1: library part R0058-A.5, "RES CHIP 0402 1M 1% 1/16W", Case Code (Imperial)=0402, Case Code (Metric)=1005, Manufacturer=Vishay, Manufacturer 2=Panasonic, Manufacturer Part Number 2=ERJ-2RKF1004X, Power=63mW, Tolerance=1%
R2 R13 R14 R15 R25: library part R0149-A.4, "RES CHIP 0201 330R 1% 1/20W", Case Code (Imperial)=0201, Case Code (Metric)=0603, Manufacturer=Yageo, Manufacturer 2="Samsung Electro-Mechanics", Manufacturer Part Number 2=RC0603F331CS, Power=50mW, Tolerance=1%
R3 R16 R17 R18 R20 R22 R28 RPAD: library part R0140-A.4, "RES CHIP 0201 0R 1/20W 5%", Case Code (Imperial)=0201, Case Code (Metric)=0603, Manufacturer=Vishay, Power=50mW, Tolerance=5%
R4 R5: library part R0197-A.2, "RES CHIP 0201 27R 1/20W 5%", Case Code (Imperial)=0201, Case Code (Metric)=0603, Manufacturer=Vishay, Manufacturer 2=Panasonic, Manufacturer Part Number 2=ERJ-U01F27R0C, Power=50mW, Tolerance=1%
R6 R23: library part R0198-A.1, "RES CHIP 0201 976k 1/20W 1%", Manufacturer="Stackpole Electronics Inc", Tolerance=1%
R7 R8: library part R0199-A.1, "RES CHIP 0201 220k 1% 1/20W", Manufacturer=Yageo, Tolerance=1%
R9 R10 R11 R12 R19: library part R0151-A.4, "RES CHIP 0201 4K7 1% 1/20W", Case Code (Imperial)=0201, Case Code (Metric)=0603, Manufacturer=Yageo, Power=50mW, Tolerance=1%
SJ1: library part UT0002-A.3, "Solder Jumper 0805"
SJ2: library part UT0033-A.6, Manufacturer=Vishay, Part Number=CRCW02010000Z0ED
SJ4: library part UT0006-A.10, "Solder Jumper shorted pads"
U1: library part U0177-A.10, "IC MICROCONTROLLER RASPBERRY PI", Manufacturer=Raspberry
U2: library part M0002-A.5, "MODULE ESP32 WiFi/BLE", Manufacturer=UBlox
U4: library part U0034-A.4, "IC AUTHENTICATION CHIP UDFN8", Manufacturer=Microchip
U5: library part U0197-A.3, "IC FLASH 128MB 6DFN 3V", Manufacturer="Adesto Technologies"
U6: library part U0072-A.5, "IC STEP DOWN CONV 1A 22V QFN8", Manufacturer="Monolithic Power Systems"
U7: library part X0013-A.3, "MEMS OSC 12MHz VDD 1.7V to 3.6V VFLGA 1.6mm x 1.2mm", Manufacturer=Microchip
U8: library part U0074-A.4, "SENS MEMS AUDIO OMNIDIRECTIONAL", Manufacturer=STMicroelectronics
U9: library part U0179-A.4, "IMU ACCEL/GYRO I2C/SPI 14VFLGA", Case/Package=LGA-14L, Manufacturer=STMicroelectronics, Max Operating Temperature=+85, Max Supply Voltage=3.6V, Min Operating Temperature=-40, Min Supply Voltage=1.7V

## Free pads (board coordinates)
  round 1.651 hole 1.651 unplated: MH(1.264,1.261) MH(1.264,16.501) MH(41.904,1.261) MH(41.904,16.501)

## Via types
v1: diameter 0.4, hole 0.2, TOP to BOTTOM, tented both sides, 198 vias

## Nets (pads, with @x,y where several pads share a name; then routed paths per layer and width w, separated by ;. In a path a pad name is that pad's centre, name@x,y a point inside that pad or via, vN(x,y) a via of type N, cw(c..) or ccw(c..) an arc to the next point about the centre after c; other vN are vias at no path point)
+1V1: C10.1 C24.1 C33.2 U1.23 U1.45 U1.50 | length 21.8
  TOP w0.15: C24.1@20.137,4.044 20.608,4.044 20.723,4.16 20.723,4.643 20.904,4.824 20.904,6.019 20.932,6.047 20.932,6.239 21.004,6.312 U1.45@21.004,6.791 21.004,7.51 21.503,8.009 22.735,8.009 ; C33.2@20.137,4.614 20.152,4.599 20.723,4.599 ; C10.1@22.134,14.416 22.13,14.412 22.13,14.128 22.204,14.053 U1.23@22.204,13.541 22.204,12.866 22.316,12.754 v1(22.316,12.686) ; U1.50@23.004,6.791 23.004,7.251 22.735,7.521 22.735,8.009 ; v1(24.795,9.537) 24.795,8.639 24.489,8.333 23.06,8.333 22.735,8.009
  SIG w0.15: v1(20.234,10.883) 20.301,10.883 20.445,11.027 23.624,11.027 24.229,10.422 24.229,10.015 24.329,9.915 24.329,9.91 24.578,9.661 24.603,9.661 24.726,9.538 v1@24.814,9.538
  BOTTOM w0.15: v1(20.234,10.883) 21.311,10.883 22.316,11.888 v1(22.316,12.686)
+3V3: C5.1 C6.1 C7.1 C11.1 C12.1 C13.1 C14.1 C15.1 C16.1 C17.2 C18.1 C21.1 C26.1 C27.1 C28.1 C30.1 C32.1 DL2.A DL3.1 JP2.2 L1.2 R2.2 R7.2 R9.2 R10.2 R11.2 R12.2 R19.2 SJ4.1 TP_3V3.X U1.1 U1.10 U1.22 U1.33 U1.42 U1.44 U1.48 U1.49 U2.9 U2.10 U4.8 U5.8 U7.1 U7.4 U8.1 U8.2 U9.5 U9.8 U9.12 | length 55.4
  TOP w0.15: v1(0.494,14.541) 1.119,14.541 DL2.A@1.169,14.591 ; R2.2@5.094,3.041 5.097,3.039 5.097,2.509 JP2.2@6.344,1.261 ; DL3.1@7.481,11.493 DL3.1@7.484,11.496 7.916,11.496 8.019,11.6 8.019,12.776 v1(7.979,12.817) 7.953,12.817 7.711,13.059 C28.1@7.711,13.296 ; v1(16.624,7.378) 16.625,7.379 17.17,7.379 C26.1@17.171,7.381 U5.8@17.171,8.331 ; v1(17.895,3.976) 17.931,3.976 18.468,4.513 L1.2@18.564,4.513 ; R11.2@18.45,14.416 18.45,14.028 17.847,13.425 17.847,12.599 18.096,12.35 C21.1@18.45,12.35 18.45,11.719 18.542,11.628 v1(18.542,11.574) 18.949,11.166 U1.33@19.429,11.166 ; U1.42@19.429,7.566 19.439,7.557 20.489,7.557 v1(20.528,7.518) 20.528,7.45 20.604,7.374 U1.44@20.604,6.791 20.604,6.136 20.495,6.026 C13.1@20.495,5.721 ; v1(19.573,3.423) R9.2@20.043,3.422 ; C18.1@19.928,5.732 19.928,5.95 20.052,6.074 20.542,6.074 ; R9.2@20.044,3.422 R10.2@20.676,3.421 ; U1.48@22.204,6.791 22.204,6.233 22.39,6.048 22.604,6.048 ; U1.49@22.604,6.791 22.604,6.048 ; C11.1@22.712,14.387 22.712,14.186 22.604,14.078 U1.22@22.604,13.541 22.604,12.999 22.895,12.709 v1(22.895,12.676) ; U9.8@22.896,4.881 22.455,4.881 22.217,4.643 C6.1@21.995,4.643 ; U9.12@23.771,3.031 23.771,2.473 23.654,2.355 22.624,2.355 21.995,2.984 C32.1@21.995,3.443 C30.1@21.995,4.043 C6.1@21.995,4.643 ; v1(24.764,5.994) 24.764,5.938 24.771,5.931 U9.5@24.771,5.331 ; R12.2@25.788,14.762 26.139,14.762 26.609,15.231 28.139,15.231 28.227,15.144 U7.1@28.227,14.708 28.589,14.708 28.695,14.602 C14.1@28.989,14.602 28.988,14.203 28.844,14.059 v1(28.844,13.991) ; U1.1@26.179,7.566 26.543,7.566 26.568,7.591 26.582,7.591 26.62,7.629 27.059,7.629 27.191,7.761 v1(27.258,7.761) 27.279,7.74 27.279,7.418 C12.1@27.299,7.397 ; U1.10@26.179,11.166 26.189,11.157 26.653,11.157 26.763,11.047 27.434,11.047 C7.1@27.491,11.104 27.503,11.104 27.754,10.853 27.754,10.62 v1(27.802,10.572) ; U4.8@28.409,3.201 28.409,3.558 v1(28.76,3.909) 28.798,3.871 29.035,3.871 29.219,3.687 C27.1@29.219,3.442 ; v1(33.894,14.129) 34.418,14.653 R7.2@35.369,14.653 ; R19.2@34.313,3.442 34.316,3.44 34.316,2.96 v1(34.319,2.957) ; C6.1@21.995,4.643 C5.1@21.995,5.243 22.265,5.243 22.547,5.525 22.547,5.595 22.604,5.653 22.604,6.048
  TOP w0.2: C17.2@14.571,7.231 14.695,7.355 15.433,7.355 15.436,7.357 16.603,7.357 v1(16.624,7.378) ; U7.4@28.277,13.958 28.294,13.975 28.828,13.975 v1(28.844,13.991) ; C15.1@37.163,3.442 37.163,3.663 37.4,3.9 37.8,3.9 37.919,4.019 U2.9@37.919,4.756 ; C16.1@38.344,3.453 38.549,3.453 38.897,3.801 38.897,4.734 U2.10@38.919,4.756
  TOP w0.4: U2.9@37.919,4.756 38.069,4.906 38.069,5.594 v1(38.223,5.748) 38.419,5.748 38.769,5.397 38.769,4.906 U2.10@38.919,4.756
  BOTTOM w0.15: v1(38.223,5.748) 38.669,5.748 TP_3V3.X@39.263,6.341
  BOTTOM w0.3: v1(16.624,7.378) 16.921,7.08 SJ4.1@16.921,6.052
  BOTTOM w0.5: v1(27.258,7.761) 27.258,8.811 27.598,9.151 27.598,9.996 27.802,10.2 v1(27.802,10.572)
  other v1: 22.595,5.643 9.195,12.746 11.374,12.746
A0~: JP2.4 U1.38 | length 22.2
  TOP w0.15: v1(9.099,7.051) 9.099,7.795 9.639,8.335 9.639,9.562 10.131,10.054 11.611,10.054 12.091,10.534 12.091,11.101 v1(12.077,11.115) ; v1(18.231,8.728) 18.67,9.166 U1.38@19.429,9.166
  BOTTOM w0.15: v1(9.099,7.051) 9.606,7.051 10.181,6.476 10.181,5.692 11.409,4.463 JP2.4@11.409,1.261 ; v1(12.077,11.115) 15.663,11.115 16.88,9.899 16.88,9.109 17.233,8.756 18.202,8.756 v1(18.231,8.728)
A1~: JP2.5 U1.39 | length 21.9
  TOP w0.15: v1(9.558,7.503) 9.989,7.503 10.483,7.996 11.526,7.996 11.971,8.442 11.971,9.836 12.501,10.366 12.501,10.594 v1(12.548,10.641) ; v1(17.825,8.29) 18.394,8.29 18.871,8.766 U1.39@19.429,8.766
  BOTTOM w0.15: v1(9.558,7.503) 9.888,7.503 13.949,3.441 JP2.5@13.949,1.261 ; v1(12.548,10.641) 15.509,10.641 16.467,9.683 16.467,9.035 17.212,8.29 v1(17.825,8.29)
A2~: JP2.6 U1.40 | length 9.7
  TOP w0.15: v1(18.59,6.732) 18.59,6.799 18.438,6.951 18.438,7.909 18.895,8.366 U1.40@19.429,8.366
  BOTTOM w0.15: JP2.6@16.489,1.261 19.745,4.517 19.745,5.544 18.59,6.699 v1(18.59,6.732)
A3~: JP2.7 U1.41 | length 8.3
  TOP w0.15: v1(19.144,6.745) 19.144,6.779 18.754,7.168 18.754,7.801 18.919,7.966 U1.41@19.429,7.966
  BOTTOM w0.15: JP2.7@19.029,1.261 19.142,1.374 19.142,2.098 20.154,3.111 20.154,5.735 v1(19.144,6.745)
A4/SDA~: JP2.8 R9.1 R16.1 U1.15 U2.2 U9.14 | length 31.7
  TOP w0.15: R9.1@20.043,2.872 20.043,2.432 21.214,1.261 JP2.8@21.569,1.261 ; v1(24.671,2.231) 24.671,2.299 24.771,2.399 U9.14@24.771,3.031 U9.14@24.771,3.131 ; v1(25.406,12.519) U1.15@25.405,13.541 ; v1(30.335,3.775) 30.381,3.822 30.61,3.822 30.654,3.866 30.945,3.866 ; U2.2@30.919,4.756 30.945,4.731 30.945,3.866 ; R16.1@31.43,3.453 31.43,3.778 31.342,3.866 30.945,3.866
  SIG w0.15: JP2.8@21.569,1.261 22.87,2.562 24.671,2.562 24.671,2.55 ; v1(24.671,2.231) 24.671,2.55 ; v1(26.796,7.204) 26.796,7.9 27.182,8.286 28.271,8.286 28.624,8.639 28.907,8.639 29.344,8.639 29.719,8.264 29.719,6.066 30.335,5.45 v1(30.335,3.775) 29.945,3.775 28.758,2.588 24.709,2.588 24.671,2.55
  BOTTOM w0.15: v1(25.406,12.519) 26.101,11.823 26.101,8.892 26.783,8.21 26.783,7.217 v1(26.796,7.204)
